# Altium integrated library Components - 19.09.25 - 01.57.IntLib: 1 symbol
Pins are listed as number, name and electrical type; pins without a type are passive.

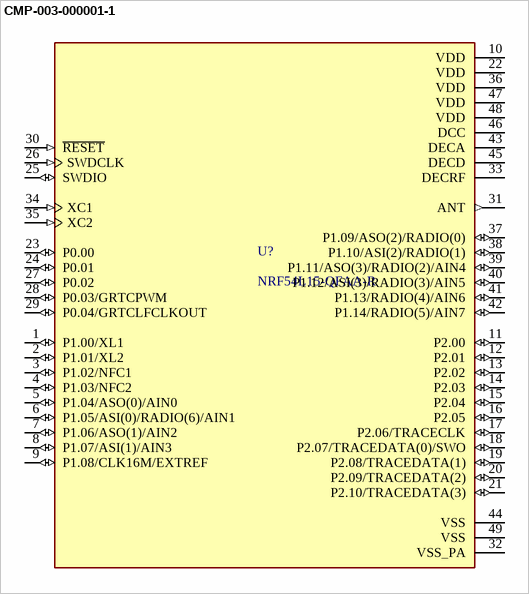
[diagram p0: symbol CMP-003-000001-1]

## CMP-003-000001-1
designator U?, comment NRF54L15-QFAA-R
MF: {'manufacturer': u'Nordic Semiconductor ASA'}
footprint QFN40P600X600X90-49N
footprint QFN40P600X600X90-49N
pins: 1 P1.00/XL1 (io), 2 P1.01/XL2 (io), 3 P1.02/NFC1 (io), 4 P1.03/NFC2 (io), 5 P1.04/ASO(0)/AIN0 (io), 6 P1.05/ASI(0)/RADIO(6)/AIN1 (io), 7 P1.06/ASO(1)/AIN2 (io), 8 P1.07/ASI(1)/AIN3 (io), 9 P1.08/CLK16M/EXTREF (io), 10 VDD (power), 11 P2.00 (io), 12 P2.01 (io), 13 P2.02 (io), 14 P2.03 (io), 15 P2.04 (io), 16 P2.05 (io), 17 P2.06/TRACECLK (io), 18 P2.07/TRACEDATA(0)/SWO (io), 19 P2.08/TRACEDATA(1) (io), 20 P2.09/TRACEDATA(2) (io), 21 P2.10/TRACEDATA(3) (io), 22 VDD (power), 23 P0.00 (io), 24 P0.01 (io), 25 SWDIO (io), 26 SWDCLK (in), 27 P0.02 (io), 28 P0.03/GRTCPWM (io), 29 P0.04/GRTCLFCLKOUT (io), 30 ~{RESET} (in), 31 ANT (out), 32 VSS_PA (power), 33 DECRF (power), 34 XC1 (in), 35 XC2 (in), 36 VDD (power), 37 P1.09/ASO(2)/RADIO(0) (io), 38 P1.10/ASI(2)/RADIO(1) (io), 39 P1.11/ASO(3)/RADIO(2)/AIN4 (io), 40 P1.12/ASI(3)/RADIO(3)/AIN5 (io), 41 P1.13/RADIO(4)/AIN6 (io), 42 P1.14/RADIO(5)/AIN7 (io), 43 DECA (power), 44 VSS (power), 45 DECD (power), 46 DCC (power), 47 VDD (power), 48 VDD (power), 49 VSS (power)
